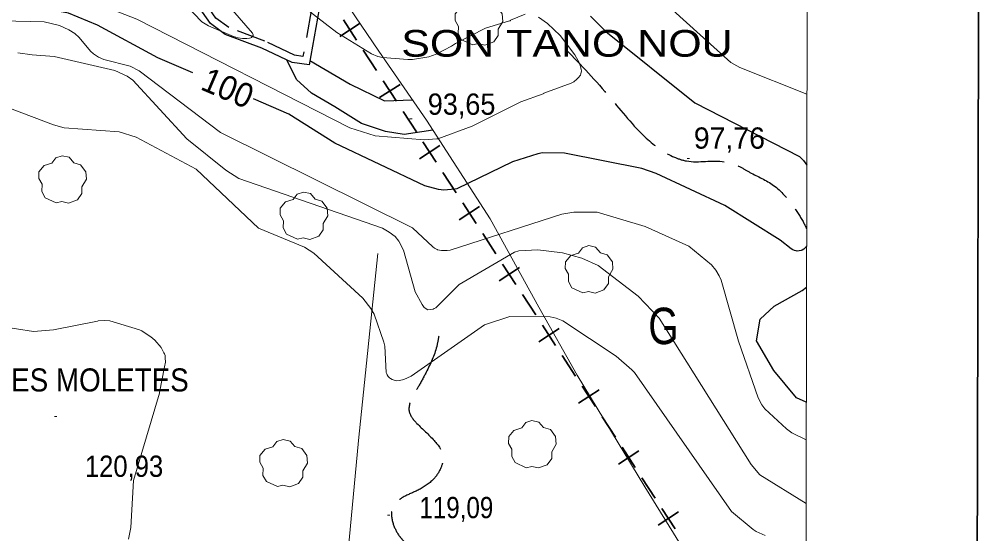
# Model space of a CAD drawing. Extents: x 480264 to 484872, y 4381275 to 4384491.
# Drawn here: x 483775.7 to 484171.3, y 4383600 to 4383811.8 of the extents above; entities that cross this region are included whole.
import ezdxf
from ezdxf.enums import TextEntityAlignment as Align

# ---------------------------------------------------------------- set-up
doc = ezdxf.new("R2010")
doc.units = 0
doc.header["$LTSCALE"] = 4
doc.linetypes.add('LONG_DASHED', pattern=[7.5, 6, -1.5])
doc.linetypes.add('MEDIUM_DASHED', pattern=[4.5, 3, -1.5])
for name, color, linetype, lineweight in [('1', 7, 'Continuous', 13), ('25', 7, 'LONG_DASHED', 25), ('29', 7, 'Continuous', 13), ('34', 7, 'Continuous', 35), ('38', 7, 'Continuous', 25), ('51', 7, 'Continuous', 13), ('7', 7, 'Continuous', 13), ('8', 7, 'Continuous', 25), ('9', 7, 'Continuous', 13)]:
    doc.layers.add(name, color=color, linetype=linetype, lineweight=lineweight)
doc.layers.add('31', color=7, linetype='Continuous')
doc.layers.add('5', color=7, linetype='Continuous')

msp = doc.modelspace()

# ---------------------------------------------------------------- linework, layer by layer
at = {"layer": '1', "lineweight": 35}
msp.add_lwpolyline([(480452.76, 4384215.91), (484171.26, 4384207.08), (484165.43, 4381752.09), (480446.93, 4381760.92)], close=True, dxfattribs=at)
at = {"layer": '1'}
msp.add_lwpolyline([(480523.1, 4384144.4), (484100.5, 4384135.8), (484095.6, 4381823.6), (480517.1, 4381832.1)], close=True, dxfattribs=at)
at = {"layer": '25'}
for points in [[(483945.9, 4383766.19), (483934.08, 4383764.39), (483926.32, 4383765.57), (483916.43, 4383768.87), (483905.54, 4383775.74), (483895.92, 4383781.38), (483889.74, 4383786.98), (483885.74, 4383795.12)], [(483895.27, 4383794.91), (483911.79, 4383785.16), (483926, 4383778.28), (483937.48, 4383778.67)], [(484099.48, 4383654.25), (484095.44, 4383655.97), (484086.16, 4383667.31), (484078.96, 4383679.52), (484080.46, 4383688.36), (484086.25, 4383693.7), (484097.72, 4383700.24), (484099.58, 4383701.59)]]:
    msp.add_lwpolyline(points, dxfattribs=at)
at = {"layer": '29'}
for points in [[(483962.24, 4383801.23), (483957.7, 4383803.35), (483956.29, 4383805.89), (483956.39, 4383808.87), (483955.02, 4383811.28), (483955.06, 4383814.03), (483957.22, 4383816.63), (483960.41, 4383817.63), (483962.06, 4383819.82), (483964.63, 4383820.65), (483967.49, 4383820), (483969.44, 4383817.73), (483972.25, 4383816.91), (483974.38, 4383814.06), (483974.62, 4383810.93), (483972.74, 4383807.78), (483972.74, 4383805.1), (483970.92, 4383802.49), (483967.3, 4383801.15), (483964.53, 4383801.78)], [(483790.92, 4383736.25), (483786.38, 4383738.37), (483784.97, 4383740.91), (483785.07, 4383743.89), (483783.7, 4383746.3), (483783.74, 4383749.05), (483785.9, 4383751.65), (483789.09, 4383752.65), (483790.74, 4383754.84), (483793.31, 4383755.67), (483796.17, 4383755.02), (483798.12, 4383752.75), (483800.93, 4383751.93), (483803.06, 4383749.08), (483803.3, 4383745.95), (483801.42, 4383742.8), (483801.42, 4383740.12), (483799.6, 4383737.51), (483795.98, 4383736.17), (483793.21, 4383736.8)], [(483890.23, 4383721.27), (483885.69, 4383723.39), (483884.28, 4383725.93), (483884.38, 4383728.91), (483883.01, 4383731.32), (483883.05, 4383734.07), (483885.21, 4383736.67), (483888.4, 4383737.67), (483890.05, 4383739.86), (483892.62, 4383740.69), (483895.48, 4383740.04), (483897.43, 4383737.77), (483900.24, 4383736.95), (483902.37, 4383734.1), (483902.61, 4383730.97), (483900.73, 4383727.82), (483900.73, 4383725.14), (483898.91, 4383722.53), (483895.29, 4383721.19), (483892.52, 4383721.82)], [(484007.57, 4383699.21), (484003.03, 4383701.33), (484001.62, 4383703.87), (484001.72, 4383706.85), (484000.35, 4383709.26), (484000.39, 4383712.01), (484002.55, 4383714.61), (484005.74, 4383715.61), (484007.39, 4383717.8), (484009.96, 4383718.63), (484012.82, 4383717.98), (484014.77, 4383715.71), (484017.58, 4383714.89), (484019.71, 4383712.04), (484019.95, 4383708.91), (484018.07, 4383705.76), (484018.07, 4383703.08), (484016.25, 4383700.47), (484012.63, 4383699.13), (484009.86, 4383699.76)], [(483984.23, 4383627.22), (483979.69, 4383629.34), (483978.28, 4383631.88), (483978.38, 4383634.86), (483977.01, 4383637.27), (483977.05, 4383640.02), (483979.21, 4383642.62), (483982.4, 4383643.62), (483984.05, 4383645.81), (483986.62, 4383646.64), (483989.48, 4383645.99), (483991.43, 4383643.72), (483994.24, 4383642.9), (483996.37, 4383640.05), (483996.61, 4383636.92), (483994.73, 4383633.77), (483994.73, 4383631.09), (483992.91, 4383628.48), (483989.29, 4383627.14), (483986.52, 4383627.77)], [(483881.89, 4383619.44), (483877.35, 4383621.56), (483875.94, 4383624.1), (483876.04, 4383627.08), (483874.67, 4383629.49), (483874.71, 4383632.24), (483876.87, 4383634.84), (483880.06, 4383635.84), (483881.71, 4383638.03), (483884.28, 4383638.86), (483887.14, 4383638.21), (483889.09, 4383635.94), (483891.9, 4383635.12), (483894.03, 4383632.27), (483894.27, 4383629.14), (483892.39, 4383625.99), (483892.39, 4383623.31), (483890.57, 4383620.7), (483886.95, 4383619.36), (483884.18, 4383619.99)]]:
    msp.add_lwpolyline(points, close=True, dxfattribs=at)
at = {"layer": '34'}
for p, q in [((483907.59, 4383804.69), (483915.96, 4383810.15)), ((483909.05, 4383811.61), (483914.5, 4383803.23)), ((483917.23, 4383799.04), (483922.69, 4383790.67)), ((483925.42, 4383786.48), (483930.88, 4383778.1)), ((483923.96, 4383779.56), (483932.34, 4383785.02)), ((483933.61, 4383773.91), (483939.07, 4383765.53)), ((483940.33, 4383754.42), (483948.71, 4383759.88)), ((483941.79, 4383761.34), (483947.25, 4383752.96)), ((483949.98, 4383748.77), (483955.44, 4383740.39)), ((483956.71, 4383729.28), (483965.09, 4383734.74)), ((483958.17, 4383736.2), (483963.63, 4383727.82)), ((483966.36, 4383723.63), (483971.81, 4383715.25)), ((483974.54, 4383711.06), (483980, 4383702.69)), ((483973.08, 4383704.15), (483981.46, 4383709.6)), ((483982.73, 4383698.5), (483988.19, 4383690.12)), ((483989.46, 4383679.01), (483997.84, 4383684.47)), ((483990.92, 4383685.93), (483996.37, 4383677.55)), ((483999.1, 4383673.36), (484004.56, 4383664.98)), ((484005.83, 4383653.87), (484014.21, 4383659.33)), ((484007.29, 4383660.79), (484012.75, 4383652.41)), ((484015.48, 4383648.22), (484020.94, 4383639.84)), ((484023.67, 4383635.65), (484029.12, 4383627.27)), ((484022.2, 4383628.73), (484030.58, 4383634.19)), ((484031.85, 4383623.08), (484037.31, 4383614.7)), ((484038.58, 4383603.6), (484046.96, 4383609.05)), ((484040.04, 4383610.51), (484045.5, 4383602.14))]:
    msp.add_line(p, q, dxfattribs=at)
at = {"layer": '38', "linetype": 'MEDIUM_DASHED'}
msp.add_lwpolyline([(483929.52, 4383858.51), (483921.23, 4383853.7), (483910.62, 4383847.02), (483896.6, 4383837.62), (483892.87, 4383831.35), (483895.97, 4383816.09), (483892.41, 4383796.53), (483888.87, 4383797.07), (483876.72, 4383802.81), (483861.91, 4383808.36), (483856.58, 4383812.3), (483845.19, 4383828.61), (483837.87, 4383834.94), (483824.01, 4383839.94), (483810.49, 4383844.18), (483799.78, 4383846.44), (483795.85, 4383848.22), (483792.47, 4383855.16), (483790.76, 4383861.93)], dxfattribs=at)
at = {"layer": '38'}
msp.add_lwpolyline([(483899.13, 4383816.13), (483894.92, 4383793.02), (483887.96, 4383794.07), (483875.51, 4383799.95), (483860.41, 4383805.61), (483854.33, 4383810.11), (483842.87, 4383826.52)], dxfattribs=at)
at = {"layer": '38', "linetype": 'LONG_DASHED'}
for points in [[(484000.68, 4383799.39), (484018.76, 4383779.56), (484033.65, 4383762.9), (484045.31, 4383755), (484050.21, 4383753.49), (484065.9, 4383753.17), (484071.99, 4383751.18), (484076.25, 4383748.81), (484086.02, 4383743.46), (484094.13, 4383734.77), (484098.37, 4383728.1), (484099.63, 4383725.57)], [(483948.27, 4383681.37), (483947.44, 4383677.16), (483943.11, 4383666.53), (483939.8, 4383660.47), (483937.44, 4383656.41), (483936.14, 4383650.27), (483939.31, 4383645.47), (483946.37, 4383638.42), (483950.03, 4383631.6), (483949.26, 4383627.51), (483946.12, 4383622.55), (483939.76, 4383618.01), (483933.67, 4383615.11), (483929.9, 4383611.7), (483929.15, 4383610.18), (483929.59, 4383603.96), (483932.34, 4383598.76), (483934.21, 4383596.54), (483940.72, 4383587.86), (483942.8, 4383584.16), (483943.86, 4383576.69), (483943.51, 4383570.58), (483939.45, 4383564.12), (483937.16, 4383558.18), (483936.44, 4383551.38), (483935.04, 4383541.91), (483934.28, 4383539.06), (483927.5, 4383518.84), (483926.82, 4383507.52), (483926.68, 4383503.83), (483926.32, 4383500.62), (483925.18, 4383491.33), (483922.04, 4383480.47), (483920.1, 4383475.28), (483915.05, 4383464.63), (483912.46, 4383457.87), (483910.9, 4383451.49), (483910.15, 4383441.41), (483909.68, 4383428.1)]]:
    msp.add_spline(points, degree=3, dxfattribs=at)
at = {"layer": '51'}
for points in [[(483986.74, 4383889), (483957.89, 4383870.69), (483913.72, 4383843.25), (483899.21, 4383834.8), (483923.65, 4383798.71), (483943.24, 4383770.31), (483969.36, 4383729.72), (483989.5, 4383693.34), (484005.24, 4383665.31), (484033, 4383619.4), (484067.74, 4383563.28), (484088.88, 4383530.13), (484099.22, 4383531.84)], [(483923.21, 4383715.44), (483915.26, 4383638.48), (483909.01, 4383571.13), (483917.15, 4383510.19), (483919.72, 4383489.5), (483897.5, 4383458.91)]]:
    msp.add_lwpolyline(points, dxfattribs=at)
at = {"layer": '7'}
for p, q in [((483936.28, 4383770.9), (483937.28, 4383770.9)), ((484050.45, 4383754.48), (484051.45, 4383754.48)), ((483790.19, 4383648.36), (483791.19, 4383648.36)), ((483927.15, 4383607.76), (483928.15, 4383607.76))]:
    msp.add_line(p, q, dxfattribs=at)
at = {"layer": '8'}
for points in [[(483847.11, 4383789.7), (483832.64, 4383795.9), (483807.9, 4383809.41), (483796.02, 4383814.29), (483693.92, 4383833.16), (483614.49, 4383878.44), (483608.15, 4383880.87), (483605.14, 4383880.98)], [(484010.77, 4383813.06), (484016.97, 4383806.72), (484053.59, 4383777.4), (484096.66, 4383755.32), (484098.29, 4383753.68), (484099.69, 4383751.83)], [(484099.62, 4383718.4), (484099.33, 4383718), (484098.5, 4383717.23), (484097.82, 4383716.81), (484097.4, 4383716.64), (484096.55, 4383716.45), (484095.7, 4383716.4), (484095.28, 4383716.44), (484094.6, 4383716.62), (484094, 4383716.88), (484093.23, 4383717.32), (484088.8, 4383720.85), (484065.91, 4383735.14), (484037.78, 4383748.29), (484031.81, 4383750.39), (484000, 4383756.77), (483990.94, 4383756.81), (483989.09, 4383756.46), (483978.64, 4383753.15), (483955.71, 4383742.02), (483954.84, 4383741.85), (483950.41, 4383741.52), (483948.17, 4383741.71), (483942.54, 4383743.3), (483905.58, 4383760.88), (483886.64, 4383772.77), (483872.05, 4383779.02)]]:
    msp.add_lwpolyline(points, dxfattribs=at)
at = {"layer": '9'}
for points in [[(483844.17, 4383837.81), (483871.71, 4383806.04), (483871.93, 4383805.43), (483871.94, 4383805.28), (483871.92, 4383805.14), (483871.66, 4383804.69), (483871.21, 4383804.35), (483870.93, 4383804.2), (483870.4, 4383804.02), (483869.37, 4383803.87), (483867.56, 4383803.89), (483865.79, 4383804.19), (483863.89, 4383804.77), (483853.53, 4383809.06), (483850.77, 4383810.74), (483834.23, 4383828.23)], [(484020.68, 4383837.19), (484068.41, 4383793.99), (484072.15, 4383791.96), (484099.75, 4383780.92)], [(483880.58, 4383826.37), (483906.35, 4383806.3), (483920.67, 4383797.52), (483923.27, 4383796.51), (483925.18, 4383796.06), (483935.52, 4383795.2), (483937.54, 4383795.22), (483944.21, 4383796.34), (483947.26, 4383797.44), (483953.54, 4383800.79), (483953.55, 4383800.79), (483955.2, 4383801.87), (483967.54, 4383808.14), (483977.42, 4383811.14), (483977.45, 4383811.14), (483977.53, 4383811.15), (483977.6, 4383811.17), (483977.65, 4383811.2), (483977.73, 4383811.26), (483977.85, 4383811.39), (483983.84, 4383813.87)], [(483989.31, 4383812.66), (483992.95, 4383810.09), (483998.21, 4383805.17), (484004.27, 4383797.14), (484006.12, 4383793.68), (484006.87, 4383791.22), (484006.94, 4383790.52), (484006.91, 4383790.03), (484006.76, 4383789.29), (484006.55, 4383788.79), (484006.37, 4383788.49), (484005.94, 4383787.94), (484005.15, 4383787.12), (484003.88, 4383786.11), (484002.78, 4383785.49), (483991.55, 4383781.38), (483991.54, 4383781.38), (483991.44, 4383781.31), (483991.17, 4383781.17), (483982.03, 4383777.8), (483982, 4383777.77), (483961.96, 4383767.81), (483947.88, 4383762.62), (483947.44, 4383762.54), (483942.28, 4383762.14), (483922.15, 4383763.85), (483911.75, 4383767.15), (483824.03, 4383811.83), (483814.14, 4383815.73)], [(484099.45, 4383638.77), (484093.58, 4383641.55), (484091.29, 4383643.19), (484082.37, 4383651.5), (484081.22, 4383653.14), (484079.66, 4383655.94), (484071.53, 4383679.38), (484064.48, 4383704.37), (484063.66, 4383706.24), (484062.33, 4383708.53), (484060.47, 4383710.77), (484051.14, 4383718.48), (484033.23, 4383726.56), (484013.43, 4383732.47), (484003.78, 4383732.35), (483998.96, 4383731.63), (483952.91, 4383716.76), (483951.78, 4383716.65), (483949.47, 4383716.62), (483947.79, 4383716.94), (483947.67, 4383716.99), (483946.58, 4383717.54), (483945.8, 4383718.09), (483937.46, 4383726.03), (483858.43, 4383765.22), (483825.05, 4383790.59), (483821.31, 4383792.54), (483810.45, 4383795.29), (483808.24, 4383796.25), (483806.2, 4383797.52), (483804.97, 4383798.63), (483800.32, 4383804.37), (483798.53, 4383805.93), (483796.14, 4383807.53), (483792.21, 4383809.26), (483785.95, 4383810.79), (483768.51, 4383811.14)], [(483775.06, 4383797.96), (483781, 4383797.14), (483790.12, 4383796.47), (483815.07, 4383790.79), (483820.04, 4383788.39), (483822.41, 4383786.81), (483844.61, 4383762.55), (483860.62, 4383749.72), (483866.03, 4383746.33), (483925.1, 4383725.78), (483927.91, 4383724.24), (483930.31, 4383722.38), (483931.82, 4383720.55), (483933.77, 4383716.77), (483938.6, 4383699.64), (483941.43, 4383694.39), (483942.33, 4383693.15), (483943.72, 4383692.26), (483943.85, 4383692.19), (483945.99, 4383692.56), (483946.41, 4383692.7), (483947.02, 4383693), (483956.61, 4383702.64), (483979.47, 4383715.97), (483981.26, 4383716.5), (483989.06, 4383716.89), (483999.15, 4383715.66), (484007.1, 4383713.47), (484013.88, 4383710.41), (484030.33, 4383697.83), (484038.9, 4383688.81)], [(484082.5, 4383599.34), (484078.9, 4383600.93), (484077.57, 4383601.82), (484068.73, 4383609.21), (484028.78, 4383666.4), (484027.72, 4383667.54), (484021.33, 4383673.19), (483999.38, 4383687.66), (483996.53, 4383688.79), (483994.08, 4383689.35), (483977.53, 4383689.45), (483967.08, 4383686.06), (483936.94, 4383664.96), (483933.85, 4383663.57), (483932.07, 4383663.13), (483931.04, 4383663.05), (483930.35, 4383663.11), (483929.94, 4383663.21), (483929.16, 4383663.5), (483928.41, 4383663.92), (483928.05, 4383664.21), (483927.49, 4383664.82), (483927.06, 4383665.47), (483926.88, 4383665.81), (483926.67, 4383666.4), (483926.03, 4383677.3), (483925.66, 4383678.89), (483921.77, 4383690.42), (483920.39, 4383692.74), (483917.01, 4383697.07), (483896.88, 4383715.56), (483893.01, 4383718.01), (483874.16, 4383725.86), (483848.48, 4383750.18), (483823.82, 4383763.31), (483816.79, 4383765.43), (483794.16, 4383767.13), (483789.72, 4383768.33), (483759.64, 4383779.8)], [(483820.62, 4383597.89), (483821.58, 4383602.62), (483822.65, 4383621.95), (483833.37, 4383657.98), (483833.33, 4383658.11), (483833.33, 4383658.14), (483835.5, 4383668.74), (483835.81, 4383670.62), (483835.74, 4383672.51), (483835.77, 4383672.59), (483835.78, 4383672.75), (483835.66, 4383673.41), (483835.43, 4383674.1), (483835.22, 4383674.56), (483834.01, 4383676.67), (483831.54, 4383679.68), (483829.89, 4383681.12), (483826.63, 4383683.18), (483826.15, 4383683.55), (483825.22, 4383684.01), (483812.99, 4383687.69), (483810.64, 4383687.81), (483808.2, 4383687.64), (483807.89, 4383687.53), (483789.81, 4383684.02), (483781.62, 4383683.24), (483767.43, 4383685.56)], [(484038.9, 4383688.81), (484076.74, 4383628.59), (484080.34, 4383624.37), (484099.39, 4383612.46)]]:
    msp.add_lwpolyline(points, dxfattribs=at)

# ---------------------------------------------------------------- texts
at = {"layer": '31', "width": 0.8}
msp.add_text('G', height=15, dxfattribs=at).set_placement((484040.74, 4383678.1), align=Align.CENTER)
at = {"layer": '5', "width": 1.2}
msp.add_text('SON TANO NOU', height=11, dxfattribs=at).set_placement((483932.86, 4383796.4))
at = {"layer": '5', "width": 0.9}
msp.add_text('SES MOLETES', height=9.5, dxfattribs=at).set_placement((483845.42, 4383658.61), align=Align.RIGHT)
at = {"layer": '7'}
for s, width, p in [('93,65', 0.95, (483943.76, 4383772.5)), ('120,93', 0.9, (483802.7, 4383623.47)), ('119,09', 0.85, (483940.3, 4383606.47))]:
    msp.add_text(s, height=8.75, dxfattribs=dict(at, width=width)).set_placement(p)
msp.add_text('97,76', height=8.75, dxfattribs=at).set_placement((484053.21, 4383758.55))
at = {"layer": '8', "width": 0.95}
msp.add_text('100', height=10, rotation=336.813, dxfattribs=at).set_placement((483859.521, 4383778.95), align=Align.CENTER)

doc.saveas('drawing.dxf')
